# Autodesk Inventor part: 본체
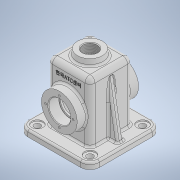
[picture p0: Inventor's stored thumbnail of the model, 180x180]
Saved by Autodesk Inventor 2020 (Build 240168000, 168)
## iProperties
Created: 2021-07
Part Number: 본체
Material: 일반
Document SubType Name: Modeling
Designer: Owner
Density: 1 g/cm^3
Appearance: 기본값
Author: Owner
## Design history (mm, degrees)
sketch "스케치1"
  geometry: L1 (26, -34)-(-26, -34); L2 (-34, -26)-(-34, 26); L3 (-26, 34)-(26, 34); L4 (34, 26)-(34, -26); L5 (34, -34)-(-34, 34); L6 (-34, -34)-(34, 34); A1 r 8 centre (26, -26) between (26, -34) and (34, -26); A2 r 8 centre (26, 26) between (34, 26) and (26, 34); A3 r 8 centre (-26, 26) between (-26, 34) and (-34, 26); A4 r 8 centre (-26, -26) between (-34, -26) and (-26, -34); 3 further points
  constraints: 12 end point, 8 point on circle, 8 point on line, 8 tangent, 4 centre point, 3 equal radius, 3 midpoint, 2 parallel, 1 coincident, 1 horizontal, 1 perpendicular
  dimensions: "d0" = 68 distance of L5.end L6.end; "d1" = 68 distance between parallel lines of L3 L1; "d2" = 8 radius of A1
extrude "돌출1" new body sketch "스케치1" distance "d3" = 105; taper "d4" = 0 deg
fillet "모깎기1" dims "d5" = 8
sketch "스케치2"
  geometry: L1 (57, -57)-(-57, -57); L2 (-57, -57)-(-57, 57); L3 (-57, 57)-(57, 57); L4 (57, 57)-(57, -57); L5 (57, -57)-(-57, 57); L6 (-57, -57)-(57, 57); L7 (29, 26)-(29, -26) reference; L8 (26, -29)-(-26, -29) reference; L9 (-29, -26)-(-29, 26) reference; L10 (-26, 29)-(26, 29) reference; L11 (34, 26)-(34, -26) reference; L12 (-26, 34)-(26, 34) reference; L13 (-34, -26)-(-34, 26) reference; L14 (26, -34)-(-26, -34) reference; A1 r 3 centre (26, 26) between (29, 26) and (26, 29) reference; A2 r 3 centre (26, -26) between (26, -29) and (29, -26) reference; A3 r 3 centre (-26, -26) between (-29, -26) and (-26, -29) reference; A4 r 3 centre (-26, 26) between (-26, 29) and (-29, 26) reference; A5 r 8 centre (26, -26) between (26, -34) and (34, -26) reference; A6 r 8 centre (26, 26) between (34, 26) and (26, 34) reference; A7 r 8 centre (-26, 26) between (-26, 34) and (-34, 26) reference; A8 r 8 centre (-26, -26) between (-34, -26) and (-26, -34) reference; 3 further points
  constraints: 12 end point, 3 midpoint, 2 parallel, 1 coincident, 1 horizontal, 1 perpendicular
  dimensions: "d7" = 114 distance between parallel lines of L2 L4; "d8" = 114 distance between parallel lines of L3 L1
  node "투영된 루프1"
feature "쉘1" dims "d6" = 5
extrude "돌출2" join sketch "스케치2" distance "d9" = 10; taper "d10" = 0 deg
fillet "모깎기2" dims "d11" = 15
sketch "스케치4"
  geometry: C1 r 5 at (-42, 42); A1 r 15 centre (-42, 42) between (-42, 57) and (-57, 42) reference; 1 further point
  constraints: 1 centre point, 1 coincident
  dimensions: "d12" = 10 diameter of C1
extrude "돌출3" cut sketch "스케치4" distance "d13" = 85.75; taper "d14" = 0 deg
sketch "스케치5"
  geometry: C1 r 5 at (-42, 42) reference; C2 r 9 at (-42, 42); 1 further point
  constraints: 1 centre point, 1 coincident
  dimensions: "d15" = 18 diameter of C2
extrude "돌출4" cut sketch "스케치5" distance "d16" = 2; taper "d17" = 0 deg
node "작업 평면2"
  node "작업 평면1"
node "작업 평면3"
sketch "스케치13"
  geometry: C1 r 20 at (0, 0); 1 further point
  constraints: 1 centre point, 1 coincident
  dimensions: "d43" = 40 diameter of C1
extrude "돌출8" join sketch "스케치13" stored distance "d44" = 17; taper "d45" = 8 deg
sketch "스케치14"
  geometry: 2 further points
  constraints: 1 coincident
hole "구멍2" sketch "스케치14" at (0, 0) diameter "d46" = 22.83494; stored, may be unused: countersink angle "d50" = 90 deg, drill point angle "d52" = 118 deg; dims "d47" = 21, "d48" = 4, "d49" = 2, "d51" = 32.05
sketch "스케치15"
  geometry: L1 (-39.984, 61.133)-(-49, 10); L2 (-57, 10)-(-42, 10) reference; L3 (-57, 10)-(-57, 0) reference; 1 further point
  constraints: 2 end point, 1 point on line
  dimensions: "d54" = 8 distance of L1.end L2.start; "d56" = 10 deg angle of L3 L1
feature "리브1" sketch "스케치15" dims "d57" = 1, "d58" = 10, "d59" = 0, "d60" = 0, "d61" = 1, "d62" = 1
fillet "모깎기3" dims "d63" = 3
fillet "모깎기4" dims "d64" = 3
chamfer "모따기2" distance "d68" = 1; stored, may be unused: second distance "d69" = 2, angle "d70" = 45 deg
fillet "모깎기5" dims "d71" = 3
fillet "모깎기6" dims "d72" = 3
sketch "스케치17"
  geometry: 1 further point
node "작업 평면4"
sketch "스케치18"
  geometry: 1 further point
sketch "스케치19"
  geometry: L1 (68, -97)-(-16, -97) reference; C1 r 28.5 at (26, -45); 2 further points
  constraints: 1 centre point, 1 midpoint, 1 vertical alignment
  dimensions: "d74" = 57 diameter of C1; "d75" = 52 distance from line of L1 C1.centre
extrude "돌출9" join sketch "스케치19" stored distance "d76" = 10; taper "d77" = 0 deg
sketch "스케치20"
  geometry: C1 r 28.5 at (0, 0) reference; C2 r 17.5 at (0, 0); 1 further point
  constraints: 1 centre point, 1 coincident
  dimensions: "d78" = 35 diameter of C2
extrude "돌출10" cut sketch "스케치20" distance "d79" = 17; taper "d80" = 0 deg
sketch "스케치21"
  geometry: C1 r 17.5 at (0, 0) reference; C2 r 15 at (0, 0); 1 further point
  constraints: 1 centre point, 1 coincident
  dimensions: "d81" = 30 diameter of C2
sketch "스케치22" dims "d82" = 44
  geometry: C1 r 28.5 at (0, 0) reference; 3 further points
  constraints: 1 coincident, 1 vertical alignment, 2 other
hole "구멍3" sketch "스케치22" at (0, 22) diameter "d83" = 3.242; stored, may be unused: countersink angle "d87" = 90 deg, drill point angle "d89" = 118 deg; dims "d84" = 8, "d85" = 4, "d86" = 2, "d88" = 10
extrude "돌출11" cut sketch "스케치21" extent not by distance; stored distance "d93" = 17; taper "d94" = 0 deg
chamfer "모따기3" distance "d95" = 1; stored, may be unused: second distance "d96" = 2, angle "d97" = 45 deg
fillet "모깎기7" dims "d98" = 3
sketch "스케치23"
  geometry: 1 further point
fillet "모깎기8" dims "d99" = 0.3
fillet "모깎기9" dims "d100" = 0.3
sketch "스케치24"
  geometry: L1 (46, 18)-(6, 18) reference; C1 r 28.5 at (26, -45) reference; 2 further points
  constraints: 1 vertical alignment, 1 other
  dimensions: "d101" = 25 distance from line of point (26, -7) L1
feature "엠보싱1" sketch "스케치24" dims "d102" = 0.5, "d103" = 0
node "솔리드1"
mirror "미러1"
mirror "미러2"
mirror "미러4"
pattern_circular "원형 패턴2" dims angle "d91" = 360 deg
mirror "미러5"
feature "A9D066F2-1C7D-4E18-AEED-F7BC21143FA4" dims "d46" = 22.83494, "d47" = 21, "d48" = 4, "d49" = 2, "d50" = 90 deg, "d51" = 32.05, "d52" = 118 deg
other parameters: "d18" = 15, "d42" = 115, "d73" = 15
